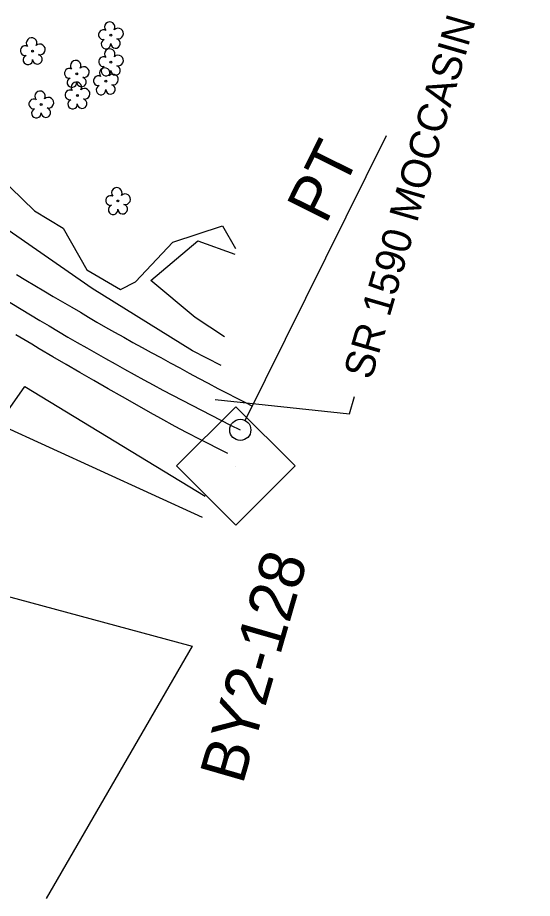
# Model space of a CAD drawing. Extents: x 479429 to 482809, y 488118 to 492379.
# Drawn here: x 481621 to 481803.4, y 490831.1 to 491143.2 of the extents above; entities that cross this region are included whole.
import ezdxf

# ---------------------------------------------------------------- set-up
doc = ezdxf.new("R2010")
doc.units = 0
for name, color, linetype in [('CTL Secondary Horizontal and Vertical CELL', 7, 'Continuous'), ('CTL Secondary Horizontal and Vertical Text', 7, 'Continuous'), ('Exist Horizontal Alignment', 7, 'Continuous'), ('Exist Roads EOP', 7, 'Continuous'), ('Exist Roads EOP Leader', 7, 'Continuous'), ('Exist Roads EOP Text', 7, 'Continuous'), ('Exist Vegetation Hedge Row', 7, 'Continuous'), ('Exist Vegetation Tree CELL', 7, 'Continuous'), ('Exist Vegetation Woods Line', 7, 'Continuous')]:
    doc.layers.add(name, color=color, linetype=linetype)

msp = doc.modelspace()

# ---------------------------------------------------------------- linework, layer by layer
at = {"layer": 'CTL Secondary Horizontal and Vertical CELL'}
msp.add_line((481698.24, 490984.29), (481698.24, 490984.29), dxfattribs=at)
msp.add_lwpolyline([(481677.38, 490984.36), (481698.35, 491005.33), (481719.35, 490984.33), (481698.39, 490963.36)], close=True, dxfattribs=at)
at = {"layer": 'Exist Horizontal Alignment'}
msp.add_line((481701.6, 491000.48), (481751.71, 491101.45), dxfattribs=at)
msp.add_circle((481699.93, 490997.12), 3.75, dxfattribs=at)
msp.add_arc((482162.41, 491929.04), 1040.37, 230.0189, 243.60668, dxfattribs=at)
at = {"layer": 'Exist Roads EOP'}
for points in [[(481620.7, 491052.17), (481623.9, 491050.22), (481627.09, 491048.31), (481630.36, 491046.37), (481633.68, 491044.41), (481636.98, 491042.48), (481640.22, 491040.59), (481643.28, 491038.79), (481646.18, 491037.07), (481649.14, 491035.33), (481652.19, 491033.55), (481655.37, 491031.75), (481658.66, 491029.92), (481661.91, 491028.13), (481665.11, 491026.36), (481668.38, 491024.57), (481671.73, 491022.74), (481675.12, 491020.9), (481678.53, 491019.07), (481681.87, 491017.26), (481685.17, 491015.46), (481688.54, 491013.65), (481691.98, 491011.82), (481695.29, 491010.09), (481698.44, 491008.48), (481701.5, 491006.92), (481704.29, 491005.52)], [(481695.57, 490988.72), (481691.72, 490990.68), (481688.81, 490992.16), (481685.92, 490993.62), (481680.92, 490996.18), (481676.87, 490998.29), (481671.72, 491001.11), (481668.07, 491003.18), (481663.38, 491005.85), (481658.21, 491008.8), (481653.12, 491011.69), (481648.08, 491014.57), (481643.08, 491017.46), (481638.2, 491020.31), (481633.53, 491023.03), (481628.69, 491025.88), (481626.05, 491027.46), (481623.27, 491029.13), (481620.44, 491030.85)]]:
    msp.add_lwpolyline(points, dxfattribs=at)
at = {"layer": 'Exist Roads EOP Leader'}
msp.add_lwpolyline([(481690.97, 491007.87), (481738.65, 491002.85), (481740.42, 491008.95)], dxfattribs=at)
at = {"layer": 'Exist Vegetation Hedge Row'}
msp.add_lwpolyline([(481693.11, 491019.92), (481682.98, 491025.16), (481647.39, 491047.24), (481600.97, 491079.44), (481578.86, 491090.84), (481567.39, 491108.08), (481590.5, 491104.37), (481605.8, 491095.22), (481626.99, 491074.71), (481637.12, 491068.6), (481645.58, 491053.82), (481657.43, 491046.86), (481662.76, 491049.54), (481676.03, 491063.65), (481693.6, 491069.41), (481698.18, 491061.41)], dxfattribs=at)
at = {"layer": 'Exist Vegetation Tree CELL'}
for p, q in [((481654.06, 491136.93), (481654.06, 491136.93)), ((481626.36, 491131.31), (481626.36, 491131.31)), ((481654.08, 491127.38), (481654.08, 491127.38)), ((481641.98, 491123.28), (481641.98, 491123.28)), ((481652.27, 491120.64), (481652.27, 491120.64)), ((481642.21, 491115.61), (481642.21, 491115.61)), ((481629.38, 491112.42), (481629.38, 491112.42)), ((481656.57, 491078.23), (481656.57, 491078.23))]:
    msp.add_line(p, q, dxfattribs=at)
for centre in [(481654.06, 491136.93), (481626.36, 491131.31), (481654.08, 491127.38), (481641.98, 491123.28), (481652.27, 491120.64), (481642.21, 491115.61), (481629.38, 491112.42), (481656.57, 491078.23)]:
    msp.add_circle(centre, 0.326, dxfattribs=at)
for centre, radius, start, end in [((481653.67, 491139.8), 1.86, 330.1651, 219.7134), ((481651.45, 491137.09), 1.73, 62.6636, 279.3457), ((481656.6, 491137.52), 1.9, 257.1011, 134.1999), ((481625.98, 491134.18), 1.86, 330.1651, 219.7134), ((481652.35, 491133.81), 1.69, 111.5671, 6.231), ((481655.73, 491134.03), 1.7, 181.2822, 74.56), ((481623.76, 491131.46), 1.73, 62.6636, 279.3457), ((481628.91, 491131.9), 1.9, 257.1011, 134.1999), ((481653.69, 491130.26), 1.86, 330.1651, 219.7134), ((481624.66, 491128.19), 1.69, 111.5671, 6.231), ((481628.04, 491128.41), 1.7, 181.2822, 74.56), ((481651.47, 491127.54), 1.73, 62.6636, 279.3457), ((481656.63, 491127.97), 1.9, 257.1011, 134.1999), ((481641.59, 491126.15), 1.86, 330.1651, 219.7134), ((481644.52, 491123.87), 1.9, 257.1011, 134.1999), ((481652.37, 491124.26), 1.69, 111.5671, 6.231), ((481655.75, 491124.48), 1.7, 181.2822, 74.56), ((481639.37, 491123.43), 1.73, 62.6636, 279.3457), ((481649.66, 491120.79), 1.73, 62.6636, 279.3457), ((481651.89, 491123.51), 1.86, 330.1651, 219.7134), ((481654.82, 491121.23), 1.9, 257.1011, 134.1999), ((481640.27, 491120.16), 1.69, 111.5671, 6.231), ((481641.82, 491118.49), 1.86, 330.1651, 219.7134), ((481643.65, 491120.38), 1.7, 181.2822, 74.56), ((481653.94, 491117.74), 1.7, 181.2822, 74.56), ((481628.99, 491115.29), 1.86, 330.1651, 219.7134), ((481639.6, 491115.77), 1.73, 62.6636, 279.3457), ((481644.76, 491116.2), 1.9, 257.1011, 134.1999), ((481650.57, 491117.52), 1.69, 111.5671, 6.231), ((481626.77, 491112.58), 1.73, 62.6636, 279.3457), ((481631.93, 491113.01), 1.9, 257.1011, 134.1999), ((481640.51, 491112.49), 1.69, 111.5671, 6.231), ((481643.88, 491112.71), 1.7, 181.2822, 74.56), ((481627.67, 491109.3), 1.69, 111.5671, 6.231), ((481631.05, 491109.52), 1.7, 181.2822, 74.56), ((481656.19, 491081.1), 1.86, 330.1651, 219.7134), ((481653.97, 491078.38), 1.73, 62.6636, 279.3457), ((481659.12, 491078.82), 1.9, 257.1011, 134.1999), ((481654.87, 491075.11), 1.69, 111.5671, 6.231), ((481658.25, 491075.33), 1.7, 181.2822, 74.56)]:
    msp.add_arc(centre, radius, start, end, dxfattribs=at)
at = {"layer": 'Exist Vegetation Woods Line'}
for points in [[(481694.35, 491030.07), (481683.98, 491036.91), (481668.21, 491050.09), (481684.83, 491064.14), (481697.94, 491059.41)], [(481686.54, 490966.1), (481614.09, 490999.09), (481623.59, 491012.51), (481687.46, 490973.62)], [(481545.33, 490841.63), (481544.99, 490846.9), (481553.47, 490860.44), (481564.99, 490867.53), (481578.8, 490897.64), (481594.78, 490944.1), (481620.43, 490937.44), (481682.93, 490920.46), (481631.17, 490831.15)]]:
    msp.add_lwpolyline(points, dxfattribs=at)

# ---------------------------------------------------------------- texts
at = {"layer": 'CTL Secondary Horizontal and Vertical Text'}
msp.add_text('BY2-128', height=16, rotation=73.904, dxfattribs=at).set_placement((481700.76, 490871.18))
at = {"layer": 'Exist Horizontal Alignment'}
msp.add_text('PT', height=16, rotation=63.6067, dxfattribs=at).set_placement((481730.19, 491069.65))
at = {"layer": 'Exist Roads EOP Text'}
msp.add_text('SR 1590 MOCCASIN CREEK RD', height=10.4, rotation=73.8069, dxfattribs=at).set_placement((481746.32, 491014.51))

doc.saveas('drawing.dxf')
